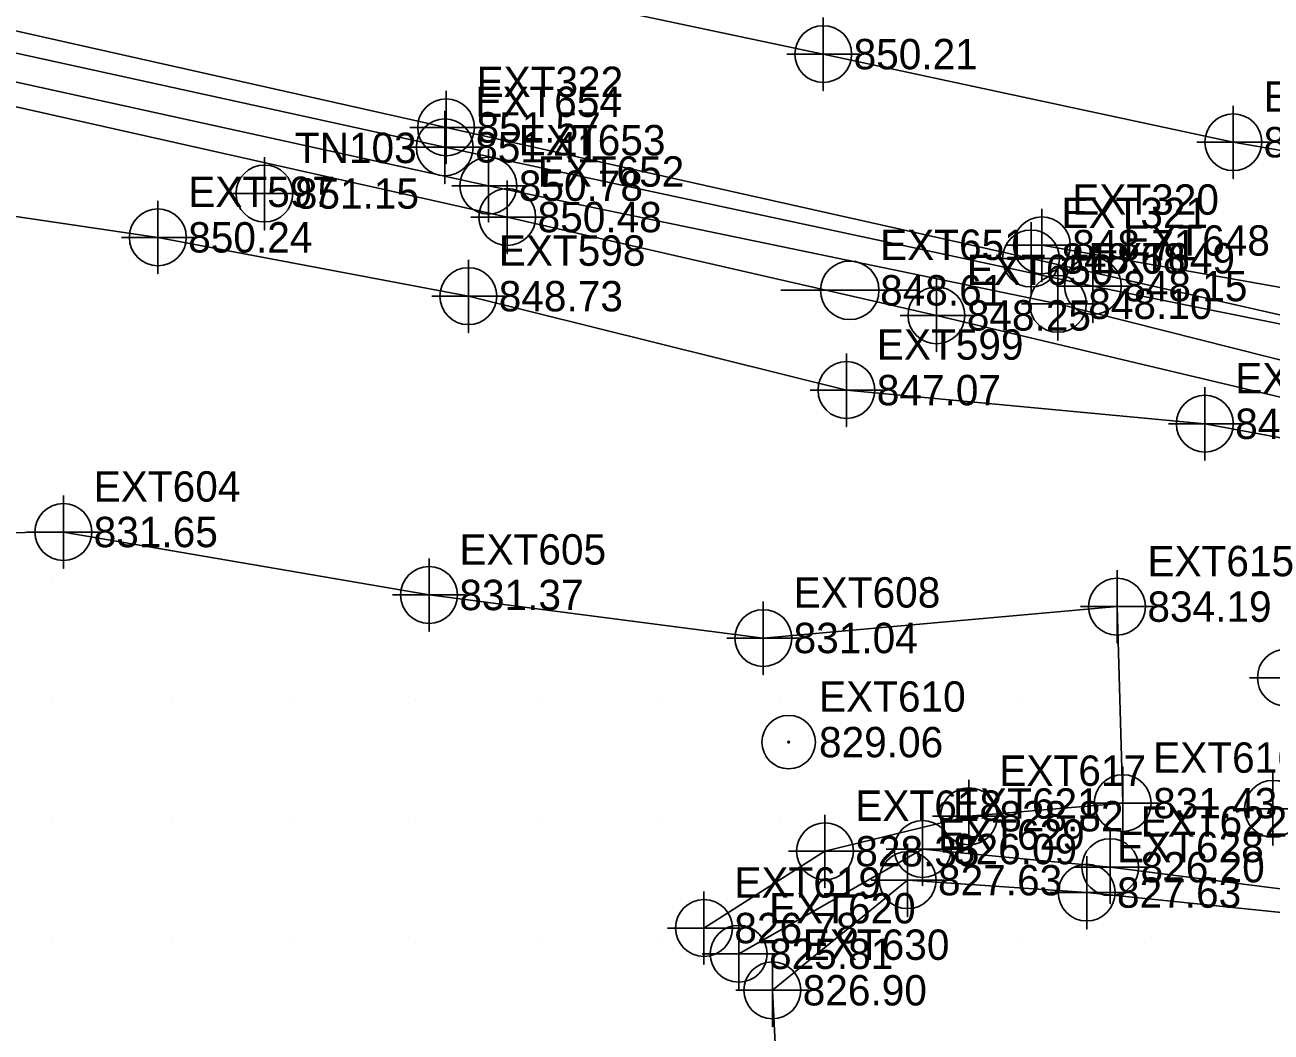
# Model space of a CAD drawing. Extents: x 1762120 to 1766775, y 709485 to 712965.
# Drawn here: x 1762807.8 to 1762910.4, y 712542.6 to 712625.5 of the extents above; entities that cross this region are included whole.
import ezdxf

# ---------------------------------------------------------------- set-up
doc = ezdxf.new("R2010")
doc.units = 0
for name, color, linetype in [('Default Symbol CELL', 7, 'Continuous'), ('Default Symbol Cogo Elevation', 7, 'Continuous'), ('Default Symbol Cogo Number', 7, 'Continuous'), ('Exist DTM Breakline', 7, 'Continuous'), ('Exist DTM Breakline Cogo Elevation', 7, 'Continuous'), ('Exist DTM Breakline Cogo Number', 7, 'Continuous'), ('Exist DTM Breakline Cogo Point CELL', 7, 'Continuous'), ('Exist DTM Crownline', 7, 'Continuous'), ('Exist DTM Crownline Cogo Elevation', 7, 'Continuous'), ('Exist DTM Crownline Cogo Number', 7, 'Continuous'), ('Exist DTM Crownline Cogo Point CELL', 7, 'Continuous'), ('Exist DTM Drainline', 7, 'Continuous'), ('Exist DTM Drainline Cogo Elevation', 7, 'Continuous'), ('Exist DTM Drainline Cogo Number', 7, 'Continuous'), ('Exist DTM Drainline Cogo Point CELL', 7, 'Continuous'), ('Exist DTM QL2 LIDAR Elevation Point', 7, 'Continuous'), ('Exist Property Iron Pin CELL', 7, 'Continuous'), ('Exist Property Iron Pin Cogo Elevation', 7, 'Continuous'), ('Exist Property Iron Pin Cogo Number', 7, 'Continuous'), ('Exist Roads EOP', 7, 'Continuous'), ('Exist Roads EOP Cogo Elevation', 7, 'Continuous'), ('Exist Roads EOP Cogo Number', 7, 'Continuous'), ('Exist Roads EOP Cogo Point CELL', 7, 'Continuous'), ('Exist Roads EOT', 7, 'Continuous'), ('Exist Roads EOT Cogo Elevation', 7, 'Continuous'), ('Exist Roads EOT Cogo Number', 7, 'Continuous'), ('Exist Roads EOT Cogo Point CELL', 7, 'Continuous'), ('Exist Utilities Telephone Pole CELL', 7, 'Continuous'), ('Exist Utilities Telephone Pole Cogo Elevation', 7, 'Continuous'), ('Exist Utilities Telephone Pole Cogo Number', 7, 'Continuous'), ('Exist Utilities Telephone UG FO SUE LOS C', 7, 'Continuous'), ('Exist Utilities Telephone UG FO SUE LOS C Cogo Elevation', 7, 'Continuous'), ('Exist Utilities Telephone UG FO SUE LOS C Cogo Number', 7, 'Continuous'), ('Exist Utilities Telephone UG FO SUE LOS C Cogo Point CELL', 7, 'Continuous'), ('Exist Utilities Water UG Line SUE LOS C', 7, 'Continuous'), ('Exist Utilities Water UG Line SUE LOS C Cogo Elevation', 7, 'Continuous'), ('Exist Utilities Water UG Line SUE LOS C Cogo Number', 7, 'Continuous'), ('Exist Utilities Water UG Line SUE LOS C Cogo Point CELL', 7, 'Continuous')]:
    doc.layers.add(name, color=color, linetype=linetype)

msp = doc.modelspace()

# ---------------------------------------------------------------- linework, layer by layer
at = {"layer": 'Default Symbol CELL'}
msp.add_lwpolyline([(1762827.55, 712614.65), (1762827.55, 712608.65), (1762827.55, 712611.65), (1762830.55, 712611.65), (1762824.55, 712611.65)], dxfattribs=at)
msp.add_circle((1762827.55, 712611.65), 2.34, dxfattribs=at)
at = {"layer": 'Exist DTM Breakline'}
for points in [[(1762719.5, 712557.51), (1762723.37, 712579.21), (1762728.17, 712592.08), (1762719.69, 712602.68), (1762720.68, 712608.52), (1762728.46, 712607.7), (1762735.49, 712603.43), (1762739.91, 712614.08), (1762743.86, 712621.24), (1762758.62, 712619.92), (1762767.95, 712615.27), (1762785.33, 712612.97), (1762818.77, 712608.04), (1762844.34, 712603.2), (1762875.47, 712595.47), (1762904.98, 712592.7), (1762941.56, 712585.95), (1762969.55, 712578.67)], [(1762744.79, 712543.26), (1762747.82, 712556.43), (1762755.63, 712584.99), (1762760.49, 712596.73), (1762788.71, 712583.59), (1762810.99, 712583.79), (1762841.1, 712578.61), (1762868.62, 712575.06), (1762897.75, 712577.65), (1762898.22, 712561.48), (1762885.56, 712560.4), (1762873.7, 712557.52), (1762863.74, 712551.2)], [(1762967.82, 712549.03), (1762948.14, 712552.08), (1762916.63, 712551.93), (1762895.25, 712554.12), (1762880.51, 712555.14), (1762869.37, 712546.08), (1762870.08, 712532.35), (1762872.62, 712514.94)]]:
    msp.add_lwpolyline(points, dxfattribs=at)
at = {"layer": 'Exist DTM Breakline Cogo Point CELL'}
for points in [[(1762818.77, 712611.04), (1762818.77, 712605.04), (1762818.77, 712608.04), (1762821.77, 712608.04), (1762815.77, 712608.04)], [(1762844.34, 712606.2), (1762844.34, 712600.2), (1762844.34, 712603.2), (1762847.34, 712603.2), (1762841.34, 712603.2)], [(1762875.47, 712598.47), (1762875.47, 712592.47), (1762875.47, 712595.47), (1762878.47, 712595.47), (1762872.47, 712595.47)], [(1762904.98, 712595.7), (1762904.98, 712589.7), (1762904.98, 712592.7), (1762907.98, 712592.7), (1762901.98, 712592.7)], [(1762810.99, 712586.79), (1762810.99, 712580.79), (1762810.99, 712583.79), (1762813.99, 712583.79), (1762807.99, 712583.79)], [(1762841.1, 712581.61), (1762841.1, 712575.61), (1762841.1, 712578.61), (1762844.1, 712578.61), (1762838.1, 712578.61)], [(1762897.75, 712580.65), (1762897.75, 712574.65), (1762897.75, 712577.65), (1762900.75, 712577.65), (1762894.75, 712577.65)], [(1762868.62, 712578.06), (1762868.62, 712572.06), (1762868.62, 712575.06), (1762871.62, 712575.06), (1762865.62, 712575.06)], [(1762911.65, 712574.8), (1762911.65, 712568.8), (1762911.65, 712571.8), (1762914.65, 712571.8), (1762908.65, 712571.8)], [(1762898.22, 712564.48), (1762898.22, 712558.48), (1762898.22, 712561.48), (1762901.22, 712561.48), (1762895.22, 712561.48)], [(1762885.56, 712563.4), (1762885.56, 712557.4), (1762885.56, 712560.4), (1762888.56, 712560.4), (1762882.56, 712560.4)], [(1762910.59, 712564.01), (1762910.59, 712558.01), (1762910.59, 712561.01), (1762913.59, 712561.01), (1762907.59, 712561.01)], [(1762873.7, 712560.52), (1762873.7, 712554.52), (1762873.7, 712557.52), (1762876.7, 712557.52), (1762870.7, 712557.52)], [(1762880.51, 712558.14), (1762880.51, 712552.14), (1762880.51, 712555.14), (1762883.51, 712555.14), (1762877.51, 712555.14)], [(1762895.25, 712557.12), (1762895.25, 712551.12), (1762895.25, 712554.12), (1762898.25, 712554.12), (1762892.25, 712554.12)], [(1762863.74, 712554.2), (1762863.74, 712548.2), (1762863.74, 712551.2), (1762866.74, 712551.2), (1762860.74, 712551.2)], [(1762869.37, 712549.08), (1762869.37, 712543.08), (1762869.37, 712546.08), (1762872.37, 712546.08), (1762866.37, 712546.08)]]:
    msp.add_lwpolyline(points, dxfattribs=at)
for centre in [(1762818.77, 712608.04), (1762844.34, 712603.2), (1762875.47, 712595.47), (1762904.98, 712592.7), (1762810.99, 712583.79), (1762841.1, 712578.61), (1762897.75, 712577.65), (1762868.62, 712575.06), (1762911.65, 712571.8), (1762898.22, 712561.48), (1762910.59, 712561.01), (1762885.56, 712560.4), (1762873.7, 712557.52), (1762880.51, 712555.14), (1762895.25, 712554.12), (1762863.74, 712551.2), (1762869.37, 712546.08)]:
    msp.add_circle(centre, 2.34, dxfattribs=at)
at = {"layer": 'Exist DTM Crownline'}
msp.add_lwpolyline([(1762166.55, 712774.69), (1762217.29, 712763.93), (1762266.93, 712753.16), (1762315.99, 712742.65), (1762361.3, 712733.13), (1762409.52, 712722.71), (1762461.51, 712711.51), (1762512.12, 712700.31), (1762561, 712689.86), (1762611.48, 712678.84), (1762663.77, 712667.96), (1762715.27, 712656.97), (1762767.73, 712645.75), (1762820.16, 712634.42), (1762873.56, 712623.12), (1762907.32, 712615.87), (1762954.84, 712607.61), (1762970.66, 712604.72)], dxfattribs=at)
at = {"layer": 'Exist DTM Crownline Cogo Point CELL'}
for points in [[(1762873.56, 712626.12), (1762873.56, 712620.12), (1762873.56, 712623.12), (1762876.56, 712623.12), (1762870.56, 712623.12)], [(1762907.32, 712618.87), (1762907.32, 712612.87), (1762907.32, 712615.87), (1762910.32, 712615.87), (1762904.32, 712615.87)]]:
    msp.add_lwpolyline(points, dxfattribs=at)
for centre in [(1762873.56, 712623.12), (1762907.32, 712615.87)]:
    msp.add_circle(centre, 2.34, dxfattribs=at)
at = {"layer": 'Exist DTM Drainline'}
msp.add_lwpolyline([(1762866.6, 712549.08), (1762881.74, 712557.7), (1762897.19, 712556.21), (1762914.64, 712553.99), (1762951.02, 712554.02)], dxfattribs=at)
at = {"layer": 'Exist DTM Drainline Cogo Point CELL'}
for points in [[(1762881.74, 712560.7), (1762881.74, 712554.7), (1762881.74, 712557.7), (1762884.74, 712557.7), (1762878.74, 712557.7)], [(1762897.19, 712559.21), (1762897.19, 712553.21), (1762897.19, 712556.21), (1762900.19, 712556.21), (1762894.19, 712556.21)], [(1762866.6, 712552.08), (1762866.6, 712546.08), (1762866.6, 712549.08), (1762869.6, 712549.08), (1762863.6, 712549.08)]]:
    msp.add_lwpolyline(points, dxfattribs=at)
for centre in [(1762881.74, 712557.7), (1762897.19, 712556.21), (1762866.6, 712549.08)]:
    msp.add_circle(centre, 2.34, dxfattribs=at)
at = {"layer": 'Exist DTM QL2 LIDAR Elevation Point'}
for p, q in [((1762810, 712580), (1762810, 712580)), ((1762810, 712570), (1762810, 712570)), ((1762820, 712570), (1762820, 712570)), ((1762830, 712570), (1762830, 712570)), ((1762840, 712570), (1762840, 712570)), ((1762850, 712570), (1762850, 712570)), ((1762860, 712570), (1762860, 712570)), ((1762870, 712570), (1762870, 712570)), ((1762880, 712570), (1762880, 712570)), ((1762890, 712570), (1762890, 712570)), ((1762810, 712560), (1762810, 712560)), ((1762820, 712560), (1762820, 712560)), ((1762830, 712560), (1762830, 712560)), ((1762840, 712560), (1762840, 712560)), ((1762850, 712560), (1762850, 712560)), ((1762860, 712560), (1762860, 712560)), ((1762870, 712560), (1762870, 712560)), ((1762810, 712550), (1762810, 712550)), ((1762820, 712550), (1762820, 712550)), ((1762830, 712550), (1762830, 712550)), ((1762840, 712550), (1762840, 712550)), ((1762850, 712550), (1762850, 712550)), ((1762860, 712550), (1762860, 712550)), ((1762880, 712550), (1762880, 712550)), ((1762890, 712550), (1762890, 712550)), ((1762900, 712550), (1762900, 712550))]:
    msp.add_line(p, q, dxfattribs=at)
at = {"layer": 'Exist Property Iron Pin CELL'}
for radius in [2.2, 0.0707]:
    msp.add_circle((1762870.71, 712566.5), radius, dxfattribs=at)
at = {"layer": 'Exist Roads EOP'}
msp.add_lwpolyline([(1762974.58, 712585.31), (1762927.98, 712597.84), (1762890.67, 712606.3), (1762842.51, 712617.09), (1762793.23, 712628.15), (1762744.7, 712638.79), (1762696.33, 712649.07), (1762645.67, 712659.58), (1762597.31, 712669.97), (1762548.88, 712680.54), (1762499.87, 712691.04), (1762451.78, 712701.31), (1762402.08, 712712.16), (1762353.64, 712722.59), (1762304.8, 712733.11), (1762255.13, 712743.65), (1762207.34, 712753.91), (1762164.28, 712763.06), (1762150.69, 712765.78)], dxfattribs=at)
at = {"layer": 'Exist Roads EOP Cogo Point CELL'}
for points in [[(1762842.51, 712620.09), (1762842.51, 712614.09), (1762842.51, 712617.09), (1762845.51, 712617.09), (1762839.51, 712617.09)], [(1762890.67, 712609.3), (1762890.67, 712603.3), (1762890.67, 712606.3), (1762893.67, 712606.3), (1762887.67, 712606.3)]]:
    msp.add_lwpolyline(points, dxfattribs=at)
for centre in [(1762842.51, 712617.09), (1762890.67, 712606.3)]:
    msp.add_circle(centre, 2.34, dxfattribs=at)
at = {"layer": 'Exist Roads EOT'}
msp.add_lwpolyline([(1762968.66, 712593.55), (1762929.23, 712600.72), (1762891.56, 712607.39)], dxfattribs=at)
at = {"layer": 'Exist Roads EOT Cogo Point CELL'}
msp.add_lwpolyline([(1762891.56, 712610.39), (1762891.56, 712604.39), (1762891.56, 712607.39), (1762888.56, 712607.39), (1762894.56, 712607.39)], dxfattribs=at)
msp.add_circle((1762891.56, 712607.39), 2.34, dxfattribs=at)
at = {"layer": 'Exist Utilities Telephone Pole CELL'}
for p, q in [((1762870.06, 712603.68), (1762881.4, 712603.68)), ((1762875.74, 712603.68), (1762875.74, 712603.68))]:
    msp.add_line(p, q, dxfattribs=at)
msp.add_circle((1762875.74, 712603.68), 2.41, dxfattribs=at)
at = {"layer": 'Exist Utilities Telephone UG FO SUE LOS C'}
for points in [[(1762975.06, 712582.94), (1762942.13, 712590.14), (1762892.88, 712602.57), (1762845.99, 712612.29), (1762766.14, 712629.83), (1762702.53, 712643.51), (1762677.77, 712648.7)], [(1762974.38, 712580.1), (1762941.96, 712587.59), (1762882.88, 712601.62), (1762847.54, 712609.71), (1762765.9, 712628.05), (1762704.22, 712639.93), (1762682.08, 712645.62)]]:
    msp.add_lwpolyline(points, dxfattribs=at)
at = {"layer": 'Exist Utilities Telephone UG FO SUE LOS C Cogo Point CELL'}
for points in [[(1762845.99, 712615.29), (1762845.99, 712609.29), (1762845.99, 712612.29), (1762848.99, 712612.29), (1762842.99, 712612.29)], [(1762847.54, 712612.71), (1762847.54, 712606.71), (1762847.54, 712609.71), (1762850.54, 712609.71), (1762844.54, 712609.71)], [(1762892.88, 712605.57), (1762892.88, 712599.57), (1762892.88, 712602.57), (1762895.88, 712602.57), (1762889.88, 712602.57)], [(1762882.88, 712604.62), (1762882.88, 712598.62), (1762882.88, 712601.62), (1762885.88, 712601.62), (1762879.88, 712601.62)]]:
    msp.add_lwpolyline(points, dxfattribs=at)
for centre in [(1762845.99, 712612.29), (1762847.54, 712609.71), (1762892.88, 712602.57), (1762882.88, 712601.62)]:
    msp.add_circle(centre, 2.34, dxfattribs=at)
at = {"layer": 'Exist Utilities Water UG Line SUE LOS C'}
msp.add_lwpolyline([(1762975.81, 712587.97), (1762937.62, 712595.56), (1762895.76, 712604.03), (1762842.4, 712615.45), (1762766.69, 712632.08), (1762701.56, 712645.98), (1762676.6, 712651.12)], dxfattribs=at)
at = {"layer": 'Exist Utilities Water UG Line SUE LOS C Cogo Point CELL'}
for points in [[(1762842.4, 712618.45), (1762842.4, 712612.45), (1762842.4, 712615.45), (1762845.4, 712615.45), (1762839.4, 712615.45)], [(1762895.76, 712607.03), (1762895.76, 712601.03), (1762895.76, 712604.03), (1762898.76, 712604.03), (1762892.76, 712604.03)]]:
    msp.add_lwpolyline(points, dxfattribs=at)
for centre in [(1762842.4, 712615.45), (1762895.76, 712604.03)]:
    msp.add_circle(centre, 2.34, dxfattribs=at)

# ---------------------------------------------------------------- texts
at = {"layer": 'Default Symbol Cogo Elevation'}
msp.add_text('851.15', height=2.5, dxfattribs=at).set_placement((1762830.05, 712610.4))
at = {"layer": 'Default Symbol Cogo Number'}
msp.add_text('TN103', height=2.5, dxfattribs=at).set_placement((1762830.05, 712614.15))
at = {"layer": 'Exist DTM Breakline Cogo Elevation'}
for s, p in [('850.24', (1762821.27, 712606.79)), ('848.73', (1762846.84, 712601.95)), ('847.07', (1762877.97, 712594.22)), ('846.29', (1762907.48, 712591.45)), ('831.65', (1762813.49, 712582.54)), ('831.37', (1762843.6, 712577.36)), ('834.19', (1762900.25, 712576.4)), ('831.04', (1762871.12, 712573.82)), ('831.43', (1762900.72, 712560.23)), ('828.82', (1762888.06, 712559.15)), ('828.35', (1762876.2, 712556.27)), ('827.63', (1762883.01, 712553.89)), ('827.63', (1762897.75, 712552.87)), ('826.78', (1762866.24, 712549.95)), ('826.90', (1762871.87, 712544.83))]:
    msp.add_text(s, height=2.5, dxfattribs=at).set_placement(p)
at = {"layer": 'Exist DTM Breakline Cogo Number'}
for s, p in [('EXT597', (1762821.27, 712610.54)), ('EXT598', (1762846.84, 712605.7)), ('EXT599', (1762877.97, 712597.97)), ('EXT601', (1762907.48, 712595.2)), ('EXT604', (1762813.49, 712586.29)), ('EXT605', (1762843.6, 712581.11)), ('EXT615', (1762900.25, 712580.15)), ('EXT608', (1762871.12, 712577.57)), ('EXT616', (1762900.72, 712563.98)), ('EXT617', (1762888.06, 712562.9)), ('EXT618', (1762876.2, 712560.02)), ('EXT629', (1762883.01, 712557.64)), ('EXT628', (1762897.75, 712556.62)), ('EXT619', (1762866.24, 712553.7)), ('EXT630', (1762871.87, 712548.58))]:
    msp.add_text(s, height=2.5, dxfattribs=at).set_placement(p)
at = {"layer": 'Exist DTM Crownline Cogo Elevation'}
for s, p in [('850.21', (1762876.06, 712621.87)), ('848.16', (1762909.82, 712614.62))]:
    msp.add_text(s, height=2.5, dxfattribs=at).set_placement(p)
at = {"layer": 'Exist DTM Crownline Cogo Number'}
msp.add_text('EXT353', height=2.5, dxfattribs=at).set_placement((1762909.82, 712618.37))
at = {"layer": 'Exist DTM Drainline Cogo Elevation'}
for s, p in [('826.09', (1762884.24, 712556.45)), ('826.20', (1762899.69, 712554.96)), ('825.81', (1762869.1, 712547.83))]:
    msp.add_text(s, height=2.5, dxfattribs=at).set_placement(p)
at = {"layer": 'Exist DTM Drainline Cogo Number'}
for s, p in [('EXT621', (1762884.24, 712560.2)), ('EXT622', (1762899.69, 712558.71)), ('EXT620', (1762869.1, 712551.58))]:
    msp.add_text(s, height=2.5, dxfattribs=at).set_placement(p)
at = {"layer": 'Exist Property Iron Pin Cogo Elevation'}
msp.add_text('829.06', height=2.5, dxfattribs=at).set_placement((1762873.21, 712565.25))
at = {"layer": 'Exist Property Iron Pin Cogo Number'}
msp.add_text('EXT610', height=2.5, dxfattribs=at).set_placement((1762873.21, 712569))
at = {"layer": 'Exist Roads EOP Cogo Elevation'}
for s, p in [('851.57', (1762845.01, 712615.84)), ('848.68', (1762893.17, 712605.05))]:
    msp.add_text(s, height=2.5, dxfattribs=at).set_placement(p)
at = {"layer": 'Exist Roads EOP Cogo Number'}
for s, p in [('EXT322', (1762845.01, 712619.59)), ('EXT321', (1762893.17, 712608.8))]:
    msp.add_text(s, height=2.5, dxfattribs=at).set_placement(p)
at = {"layer": 'Exist Roads EOT Cogo Elevation'}
msp.add_text('848.71', height=2.5, dxfattribs=at).set_placement((1762894.06, 712606.15))
at = {"layer": 'Exist Roads EOT Cogo Number'}
msp.add_text('EXT320', height=2.5, dxfattribs=at).set_placement((1762894.06, 712609.9))
at = {"layer": 'Exist Utilities Telephone Pole Cogo Elevation'}
msp.add_text('848.61', height=2.5, dxfattribs=at).set_placement((1762878.24, 712602.43))
at = {"layer": 'Exist Utilities Telephone Pole Cogo Number'}
msp.add_text('EXT651', height=2.5, dxfattribs=at).set_placement((1762878.24, 712606.18))
at = {"layer": 'Exist Utilities Telephone UG FO SUE LOS C Cogo Elevation'}
for s, p in [('850.78', (1762848.49, 712611.04)), ('850.48', (1762850.04, 712608.46)), ('848.10', (1762895.38, 712601.32)), ('848.25', (1762885.38, 712600.37))]:
    msp.add_text(s, height=2.5, dxfattribs=at).set_placement(p)
at = {"layer": 'Exist Utilities Telephone UG FO SUE LOS C Cogo Number'}
for s, p in [('EXT653', (1762848.49, 712614.79)), ('EXT652', (1762850.04, 712612.21)), ('EXT649', (1762895.38, 712605.07)), ('EXT650', (1762885.38, 712604.12))]:
    msp.add_text(s, height=2.5, dxfattribs=at).set_placement(p)
at = {"layer": 'Exist Utilities Water UG Line SUE LOS C Cogo Elevation'}
for s, p in [('851.41', (1762844.9, 712614.2)), ('848.15', (1762898.26, 712602.78))]:
    msp.add_text(s, height=2.5, dxfattribs=at).set_placement(p)
at = {"layer": 'Exist Utilities Water UG Line SUE LOS C Cogo Number'}
for s, p in [('EXT654', (1762844.9, 712617.95)), ('EXT648', (1762898.26, 712606.53))]:
    msp.add_text(s, height=2.5, dxfattribs=at).set_placement(p)

doc.saveas('drawing.dxf')
